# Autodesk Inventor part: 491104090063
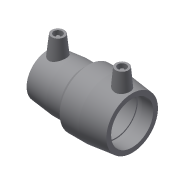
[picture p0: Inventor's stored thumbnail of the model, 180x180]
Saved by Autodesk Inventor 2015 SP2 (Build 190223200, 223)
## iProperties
Created: 2017-06
Part Number: 491104090063
Material: Generic
Description: PLASSON REDUCING COUPLER 90-63
Document SubType Name: Modeling
Designer: KIM
Mass: 54.8237 g
Surface Area: 155.252 cm^2
Volume: 54.8237 cm^3
Density: 1 g/cm^3
Appearance: Default
Author: KIM
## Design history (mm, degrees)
derived "491104.ipt"
feature "Solid1::491104.ipt"
tag "TaggingFeature1"
body "Solid1"
other parameters: "d0" = 143, "d2" = 82, "d3" = 57, "d4" = 34.2, "d5" = 73.8, "d7" = 63, "d8" = 168 deg, "d10" = 22.8, "d11" = 7.6, "d13" = 143, "d14" = 17.6296, "d15" = 57, "d18" = 63, "d19" = 2.85, "d20" = 168 deg, "d22" = 108.92847, "d25" = 135 deg, "d29" = 61, "d30" = 15, "d31" = 57.2, "d34" = 6 deg, "d35" = 15, "d38" = 26.35, "d39" = 5 deg, "d41" = 4, "d42" = 14, "d43" = 0, "d45" = 4, "d46" = 14, "d47" = 0, "d48" = 82, "d50" = 116, "d52" = 56.7, "d53" = 28.4, "d54" = 9.46667, "d55" = 168 deg, "d56" = 42.6, "d57" = 71, "d58" = 104.4, "d59" = 2.85, "d60" = 135 deg, "d61" = 78, "d62" = 15, "d64" = 4, "d66" = 5 deg, "d67" = 14, "d68" = 0, "d69" = 57.2, "d70" = 82, "d71" = 116, "d73" = 109.04, "d76" = 2.85, "d77" = 168 deg, "d79" = 2.85, "d80" = 71, "d81" = 56.7, "d82" = 77.08, "d83" = 120 deg, "d88" = 15, "d89" = 28.5, "d90" = 5 deg, "d92" = 4, "d93" = 14, "d94" = 0, "d95" = 3, "d96" = 0, "d97" = 3, "d98" = 0, "d99" = 16.53, "d100" = 4.1325, "d101" = 74.7676, "d102" = 20 deg, "d103" = 20.59, "d104" = 5.1475, "d105" = 105.7688, "d106" = 3.60705, "d107" = 3, "d108" = 0, "d109" = 3, "d110" = 0, "d_1" = 63, "L_" = 143, "L_2" = 57, "D_1" = 82, "A_1" = 61, "d_2" = 12, "L_1" = 71, "A_" = 78, "D_" = 116
